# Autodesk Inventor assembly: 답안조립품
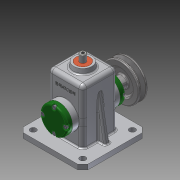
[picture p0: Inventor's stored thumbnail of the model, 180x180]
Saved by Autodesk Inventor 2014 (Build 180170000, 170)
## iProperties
Created: 2016-02
Part Number: 답안조립품
Document SubType Name: Assembly
Designer: 703-04
Author: 703-04
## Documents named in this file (16)
- C:\Users\703-04\Desktop\460212V1010[1]\답안조립품.iam
- C:\Users\703-04\Desktop\460212V1010[1]\1-본체.ipt
- C:\Users\703-04\Desktop\460212V1010[1]\V벨트풀리.ipt
- C:\Users\703-04\Desktop\460212V1010[1]\고정핀 1.2 x 10.ipt
- C:\Users\703-04\Desktop\460212V1010[1]\뒤커버.ipt
- C:\Users\703-04\Desktop\460212V1010[1]\링크.ipt
- C:\Users\703-04\Desktop\460212V1010[1]\멈춤나사 M3x8.ipt
- C:\Users\703-04\Desktop\460212V1010[1]\베어링 12 x 32 x 10.ipt
- C:\Users\703-04\Desktop\460212V1010[1]\볼트 M4 x 12.ipt
- C:\Users\703-04\Desktop\460212V1010[1]\부시.ipt
- C:\Users\703-04\Desktop\460212V1010[1]\슬라이드.ipt
- C:\Users\703-04\Desktop\460212V1010[1]\앞커버.ipt
- C:\Users\703-04\Desktop\460212V1010[1]\오일실 12 25 7.ipt
- C:\Users\703-04\Desktop\460212V1010[1]\키 4 x 4 x 10.ipt
- C:\Users\703-04\Desktop\460212V1010[1]\편심축.ipt
- C:\Users\703-04\Desktop\460212V1010[1]\핀 5 x 18.ipt
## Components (12 placed, 5 different names)
1. 1-본체:1
2. V벨트풀리:1 — 각도:2
3. 고정핀 1.2 x 10:1
4. 핀 5 x 18:1
5. ISO 4762 M4 x 12:2
6. ISO 4762 M4 x 12:3
7. ISO 4762 M4 x 12:4
8. ISO 4762 M4 x 12:5
9. ISO 4762 M4 x 12:1
10. ISO 4762 M4 x 12:6
11. ISO 4762 M4 x 12:7
12. ISO 4762 M4 x 12:8
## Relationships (1: Angle 1)
- 각도:2 [Angle]: V벨트풀리:1
